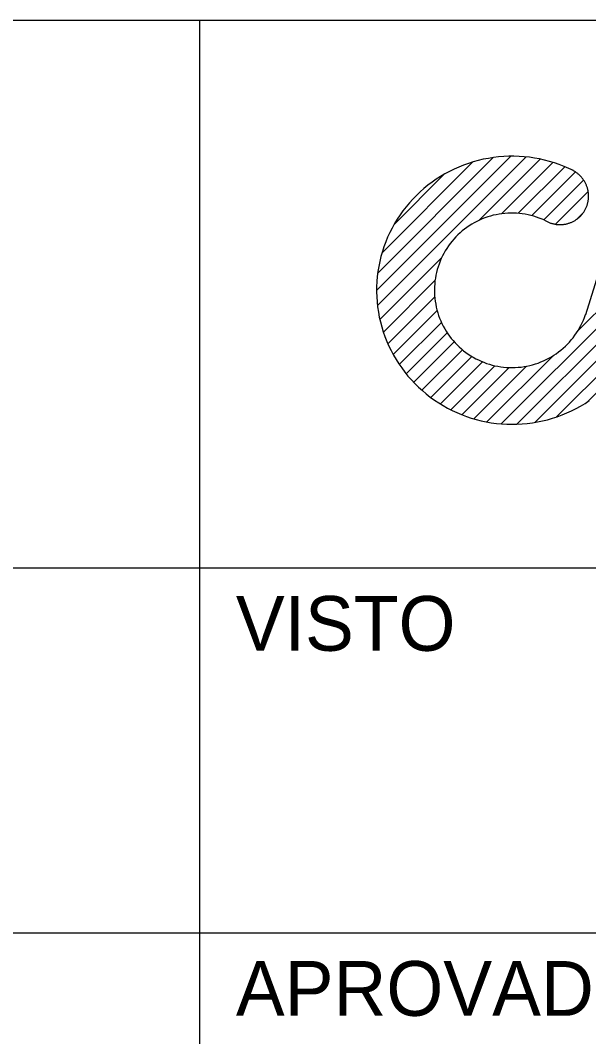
# Model space of a CAD drawing. Extents: x 563 to 1404, y 358 to 952.
# Drawn here: x 1178.67 to 1194.25, y 385.11 to 412.96 of the extents above; entities that cross this region are included whole.
import ezdxf

# ---------------------------------------------------------------- set-up
doc = ezdxf.new("R2010")
doc.units = 0
doc.layers.add('New Level (0)', color=7, linetype='Continuous')

# ---------------------------------------------------------------- blocks, each defined once
blk = doc.blocks.new('_U2')
at = {"layer": 'New Level (0)'}
for p, q in [((-15.391, 0.015), (-11.717, 3.689)), ((-15.367, -0.403), (-11.294, 3.67)), ((-15.36, 0.487), (-12.195, 3.653)), ((-12.329, 3.632), (-12.468, 3.605)), ((-12.19, 3.654), (-12.329, 3.632)), ((-12.05, 3.671), (-12.19, 3.654)), ((-11.909, 3.682), (-12.05, 3.671)), ((-11.768, 3.689), (-11.909, 3.682)), ((-11.627, 3.69), (-11.768, 3.689)), ((-11.486, 3.685), (-11.627, 3.69)), ((-11.345, 3.675), (-11.486, 3.685)), ((-11.205, 3.66), (-11.345, 3.675)), ((-11.065, 3.64), (-11.205, 3.66)), ((-10.927, 3.615), (-11.065, 3.64)), ((-15.242, 1.048), (-12.761, 3.529)), ((-13.139, 3.393), (-13.268, 3.335)), ((-13.008, 3.445), (-13.139, 3.393)), ((-12.876, 3.493), (-13.008, 3.445)), ((-12.741, 3.535), (-12.876, 3.493)), ((-12.605, 3.573), (-12.741, 3.535)), ((-12.468, 3.605), (-12.605, 3.573)), ((-12.593, 1.929), (-10.911, 3.611)), ((-11.966, 2.114), (-10.56, 3.52)), ((-11.512, 2.126), (-10.235, 3.403)), ((-10.789, 3.584), (-10.927, 3.615)), ((-10.653, 3.548), (-10.789, 3.584)), ((-10.518, 3.507), (-10.653, 3.548)), ((-10.384, 3.462), (-10.518, 3.507)), ((-10.253, 3.411), (-10.384, 3.462)), ((-10.124, 3.355), (-10.253, 3.411)), ((-9.996, 3.295), (-10.124, 3.355)), ((-14.914, 1.818), (-13.536, 3.196)), ((-13.639, 3.135), (-13.757, 3.059)), ((-13.518, 3.206), (-13.639, 3.135)), ((-13.394, 3.273), (-13.518, 3.206)), ((-13.268, 3.335), (-13.394, 3.273)), ((-11.135, 2.062), (-9.939, 3.258)), ((-9.996, 3.293), (-10.014, 3.303)), ((-9.979, 3.283), (-9.996, 3.293)), ((-9.962, 3.273), (-9.979, 3.283)), ((-9.945, 3.262), (-9.962, 3.273)), ((-9.928, 3.251), (-9.945, 3.262)), ((-9.912, 3.239), (-9.928, 3.251)), ((-9.896, 3.227), (-9.912, 3.239)), ((-9.88, 3.214), (-9.896, 3.227)), ((-9.865, 3.202), (-9.88, 3.214)), ((-9.85, 3.188), (-9.865, 3.202)), ((-9.835, 3.175), (-9.85, 3.188)), ((-9.82, 3.161), (-9.835, 3.175)), ((-9.806, 3.147), (-9.82, 3.161)), ((-9.793, 3.132), (-9.806, 3.147)), ((-9.779, 3.117), (-9.793, 3.132)), ((-9.766, 3.102), (-9.779, 3.117)), ((-9.754, 3.086), (-9.766, 3.102)), ((-9.742, 3.07), (-9.754, 3.086)), ((-9.73, 3.054), (-9.742, 3.07)), ((-14.094, 2.806), (-14.199, 2.713)), ((-13.985, 2.894), (-14.094, 2.806)), ((-13.873, 2.979), (-13.985, 2.894)), ((-13.757, 3.059), (-13.873, 2.979)), ((-10.809, 1.946), (-9.718, 3.036)), ((-9.719, 3.038), (-9.73, 3.054)), ((-9.708, 3.021), (-9.719, 3.038)), ((-9.697, 3.004), (-9.708, 3.021)), ((-9.687, 2.987), (-9.697, 3.004)), ((-9.677, 2.969), (-9.687, 2.987)), ((-9.668, 2.951), (-9.677, 2.969)), ((-9.659, 2.934), (-9.668, 2.951)), ((-8.572, 2.883), (-9.667, -0.651)), ((-9.651, 2.915), (-9.659, 2.934)), ((-9.643, 2.897), (-9.651, 2.915)), ((-9.636, 2.879), (-9.643, 2.897)), ((-9.629, 2.86), (-9.636, 2.879)), ((-9.622, 2.841), (-9.629, 2.86)), ((-9.616, 2.822), (-9.622, 2.841)), ((-9.611, 2.803), (-9.616, 2.822)), ((-9.605, 2.784), (-9.611, 2.803)), ((-14.399, 2.516), (-14.493, 2.412)), ((-14.301, 2.616), (-14.399, 2.516)), ((-14.199, 2.713), (-14.301, 2.616)), ((-10.486, 1.827), (-9.592, 2.72)), ((-9.601, 2.765), (-9.605, 2.784)), ((-9.597, 2.745), (-9.601, 2.765)), ((-9.593, 2.726), (-9.597, 2.745)), ((-9.59, 2.706), (-9.593, 2.726)), ((-9.587, 2.687), (-9.59, 2.706)), ((-9.589, 2.49), (-9.586, 2.509)), ((-9.585, 2.667), (-9.587, 2.687)), ((-9.586, 2.509), (-9.584, 2.529)), ((-9.584, 2.647), (-9.585, 2.667)), ((-9.583, 2.627), (-9.584, 2.647)), ((-9.584, 2.529), (-9.583, 2.548)), ((-9.582, 2.608), (-9.583, 2.627)), ((-9.583, 2.548), (-9.582, 2.568)), ((-9.582, 2.588), (-9.582, 2.608)), ((-9.582, 2.568), (-9.582, 2.588)), ((-14.583, 2.305), (-14.669, 2.194)), ((-14.493, 2.412), (-14.583, 2.305)), ((-9.682, 2.212), (-9.672, 2.229)), ((-9.672, 2.229), (-9.663, 2.246)), ((-9.663, 2.246), (-9.655, 2.264)), ((-9.655, 2.264), (-9.647, 2.282)), ((-9.647, 2.282), (-9.639, 2.3)), ((-9.639, 2.3), (-9.632, 2.318)), ((-9.632, 2.318), (-9.625, 2.337)), ((-9.625, 2.337), (-9.619, 2.355)), ((-9.619, 2.355), (-9.613, 2.374)), ((-9.613, 2.374), (-9.608, 2.393)), ((-9.608, 2.393), (-9.603, 2.412)), ((-9.603, 2.412), (-9.599, 2.431)), ((-9.599, 2.431), (-9.595, 2.451)), ((-9.595, 2.451), (-9.592, 2.47)), ((-9.592, 2.47), (-9.589, 2.49)), ((-14.827, 1.963), (-14.9, 1.844)), ((-14.75, 2.08), (-14.827, 1.963)), ((-14.669, 2.194), (-14.75, 2.08)), ((-12.497, 1.972), (-12.571, 1.94)), ((-12.423, 2.001), (-12.497, 1.972)), ((-12.347, 2.027), (-12.423, 2.001)), ((-12.271, 2.051), (-12.347, 2.027)), ((-12.193, 2.072), (-12.271, 2.051)), ((-12.115, 2.089), (-12.193, 2.072)), ((-12.036, 2.104), (-12.115, 2.089)), ((-11.957, 2.116), (-12.036, 2.104)), ((-11.878, 2.125), (-11.957, 2.116)), ((-11.798, 2.13), (-11.878, 2.125)), ((-11.718, 2.133), (-11.798, 2.13)), ((-11.637, 2.133), (-11.718, 2.133)), ((-11.557, 2.13), (-11.637, 2.133)), ((-11.477, 2.124), (-11.557, 2.13)), ((-11.398, 2.114), (-11.477, 2.124)), ((-11.319, 2.102), (-11.398, 2.114)), ((-11.24, 2.087), (-11.319, 2.102)), ((-11.162, 2.069), (-11.24, 2.087)), ((-11.085, 2.048), (-11.162, 2.069)), ((-11.008, 2.024), (-11.085, 2.048)), ((-10.933, 1.997), (-11.008, 2.024)), ((-10.858, 1.968), (-10.933, 1.997)), ((-10.785, 1.935), (-10.858, 1.968)), ((-9.936, 1.943), (-9.92, 1.954)), ((-9.92, 1.954), (-9.904, 1.965)), ((-9.909, 1.961), (-9.721, 2.149)), ((-9.904, 1.965), (-9.888, 1.977)), ((-9.888, 1.977), (-9.872, 1.989)), ((-9.872, 1.989), (-9.857, 2.001)), ((-9.857, 2.001), (-9.842, 2.014)), ((-9.842, 2.014), (-9.828, 2.027)), ((-9.828, 2.027), (-9.813, 2.041)), ((-9.813, 2.041), (-9.799, 2.055)), ((-9.799, 2.055), (-9.786, 2.069)), ((-9.786, 2.069), (-9.773, 2.084)), ((-9.773, 2.084), (-9.76, 2.099)), ((-9.76, 2.099), (-9.748, 2.114)), ((-9.748, 2.114), (-9.736, 2.129)), ((-9.736, 2.129), (-9.724, 2.145)), ((-9.724, 2.145), (-9.713, 2.161)), ((-9.713, 2.161), (-9.702, 2.178)), ((-9.702, 2.178), (-9.692, 2.195)), ((-9.692, 2.195), (-9.682, 2.212)), ((-14.967, 1.721), (-15.031, 1.597)), ((-14.9, 1.844), (-14.967, 1.721)), ((-12.981, 1.692), (-13.044, 1.642)), ((-12.917, 1.74), (-12.981, 1.692)), ((-12.851, 1.785), (-12.917, 1.74)), ((-12.783, 1.827), (-12.851, 1.785)), ((-12.714, 1.868), (-12.783, 1.827)), ((-12.643, 1.905), (-12.714, 1.868)), ((-12.571, 1.94), (-12.643, 1.905)), ((-10.788, 1.936), (-10.77, 1.926)), ((-10.77, 1.926), (-10.753, 1.916)), ((-10.753, 1.916), (-10.735, 1.907)), ((-10.735, 1.907), (-10.717, 1.898)), ((-10.717, 1.898), (-10.699, 1.89)), ((-10.699, 1.89), (-10.68, 1.882)), ((-10.68, 1.882), (-10.662, 1.874)), ((-10.662, 1.874), (-10.643, 1.867)), ((-10.643, 1.867), (-10.624, 1.86)), ((-10.624, 1.86), (-10.605, 1.854)), ((-10.605, 1.854), (-10.586, 1.849)), ((-10.586, 1.849), (-10.566, 1.843)), ((-10.566, 1.843), (-10.547, 1.839)), ((-10.547, 1.839), (-10.527, 1.834)), ((-10.527, 1.834), (-10.508, 1.831)), ((-10.508, 1.831), (-10.488, 1.827)), ((-10.488, 1.827), (-10.468, 1.824)), ((-10.468, 1.824), (-10.448, 1.822)), ((-10.448, 1.822), (-10.428, 1.82)), ((-10.428, 1.82), (-10.409, 1.819)), ((-10.409, 1.819), (-10.389, 1.818)), ((-10.389, 1.818), (-10.369, 1.818)), ((-10.369, 1.818), (-10.349, 1.818)), ((-10.349, 1.818), (-10.329, 1.819)), ((-10.329, 1.819), (-10.309, 1.82)), ((-10.309, 1.82), (-10.289, 1.821)), ((-10.289, 1.821), (-10.269, 1.824)), ((-10.269, 1.824), (-10.249, 1.826)), ((-10.249, 1.826), (-10.23, 1.829)), ((-10.23, 1.829), (-10.21, 1.833)), ((-10.21, 1.833), (-10.191, 1.837)), ((-10.191, 1.837), (-10.171, 1.841)), ((-10.171, 1.841), (-10.152, 1.846)), ((-10.152, 1.846), (-10.133, 1.852)), ((-10.133, 1.852), (-10.114, 1.858)), ((-10.114, 1.858), (-10.096, 1.864)), ((-10.096, 1.864), (-10.077, 1.871)), ((-10.077, 1.871), (-10.059, 1.879)), ((-10.059, 1.879), (-10.04, 1.887)), ((-10.04, 1.887), (-10.022, 1.895)), ((-10.022, 1.895), (-10.005, 1.904)), ((-10.005, 1.904), (-9.987, 1.913)), ((-9.987, 1.913), (-9.97, 1.922)), ((-9.97, 1.922), (-9.953, 1.932)), ((-9.953, 1.932), (-9.936, 1.943)), ((-15.089, 1.47), (-15.142, 1.341)), ((-15.031, 1.597), (-15.089, 1.47)), ((-13.273, 1.42), (-13.325, 1.359)), ((-13.219, 1.478), (-13.273, 1.42)), ((-13.163, 1.535), (-13.219, 1.478)), ((-13.104, 1.59), (-13.163, 1.535)), ((-13.044, 1.642), (-13.104, 1.59)), ((-9.882, -1.105), (-7.37, 1.406)), ((-15.19, 1.21), (-15.234, 1.077)), ((-15.142, 1.341), (-15.19, 1.21)), ((-13.467, 1.165), (-13.509, 1.098)), ((-13.422, 1.232), (-13.467, 1.165)), ((-13.375, 1.296), (-13.422, 1.232)), ((-13.325, 1.359), (-13.375, 1.296)), ((-15.272, 0.943), (-15.305, 0.807)), ((-15.302, -0.78), (-13.605, 0.917)), ((-15.234, 1.077), (-15.272, 0.943)), ((-13.62, 0.885), (-13.651, 0.812)), ((-13.586, 0.957), (-13.62, 0.885)), ((-13.549, 1.028), (-13.586, 0.957)), ((-13.509, 1.098), (-13.549, 1.028)), ((-15.333, 0.671), (-15.355, 0.533)), ((-15.305, 0.807), (-15.333, 0.671)), ((-13.729, 0.585), (-13.749, 0.508)), ((-13.706, 0.662), (-13.729, 0.585)), ((-13.68, 0.737), (-13.706, 0.662)), ((-13.651, 0.812), (-13.68, 0.737)), ((-11.977, -3.642), (-7.564, 0.771)), ((-15.372, 0.395), (-15.384, 0.256)), ((-15.355, 0.533), (-15.372, 0.395)), ((-15.206, -1.126), (-13.788, 0.292)), ((-13.78, 0.351), (-13.791, 0.272)), ((-13.766, 0.43), (-13.78, 0.351)), ((-13.749, 0.508), (-13.766, 0.43)), ((-15.39, 0.116), (-15.392, -0.023)), ((-15.384, 0.256), (-15.39, 0.116)), ((-13.805, 0.113), (-13.807, 0.033)), ((-13.807, 0.033), (-13.806, -0.047)), ((-13.8, 0.193), (-13.805, 0.113)), ((-13.791, 0.272), (-13.8, 0.193)), ((-11.545, -3.652), (-7.758, 0.135)), ((-15.392, -0.023), (-15.387, -0.162)), ((-15.387, -0.162), (-15.378, -0.301)), ((-15.083, -1.445), (-13.799, -0.161)), ((-13.806, -0.047), (-13.802, -0.127)), ((-13.802, -0.127), (-13.795, -0.206)), ((-13.795, -0.206), (-13.785, -0.285)), ((-15.378, -0.301), (-15.363, -0.44)), ((-15.363, -0.44), (-15.343, -0.578)), ((-14.937, -1.741), (-13.732, -0.536)), ((-13.785, -0.285), (-13.772, -0.364)), ((-13.772, -0.364), (-13.756, -0.442)), ((-13.756, -0.442), (-13.737, -0.52)), ((-13.737, -0.52), (-13.716, -0.597)), ((-11.053, -3.602), (-7.952, -0.501)), ((-15.343, -0.578), (-15.317, -0.715)), ((-15.317, -0.715), (-15.286, -0.851)), ((-13.716, -0.597), (-13.691, -0.673)), ((-13.691, -0.673), (-13.664, -0.748)), ((-13.664, -0.748), (-13.633, -0.822)), ((-13.633, -0.822), (-13.6, -0.894)), ((-9.755, -0.872), (-9.723, -0.799)), ((-9.723, -0.799), (-9.693, -0.725)), ((-9.693, -0.725), (-9.667, -0.649)), ((-15.286, -0.851), (-15.25, -0.986)), ((-15.25, -0.986), (-15.209, -1.119)), ((-14.77, -2.015), (-13.615, -0.861)), ((-13.6, -0.894), (-13.564, -0.966)), ((-13.564, -0.966), (-13.526, -1.036)), ((-13.526, -1.036), (-13.485, -1.104)), ((-13.485, -1.104), (-13.441, -1.171)), ((-9.911, -1.151), (-9.868, -1.083)), ((-9.868, -1.083), (-9.828, -1.014)), ((-9.828, -1.014), (-9.79, -0.944)), ((-9.79, -0.944), (-9.755, -0.872)), ((-15.209, -1.119), (-15.163, -1.251)), ((-15.163, -1.251), (-15.112, -1.381)), ((-15.112, -1.381), (-15.055, -1.509)), ((-14.582, -2.269), (-13.458, -1.145)), ((-13.441, -1.171), (-13.395, -1.237)), ((-13.395, -1.237), (-13.346, -1.3)), ((-13.346, -1.3), (-13.295, -1.362)), ((-13.295, -1.362), (-13.242, -1.421)), ((-10.463, -3.453), (-8.146, -1.137)), ((-10.107, -1.403), (-10.055, -1.343)), ((-10.055, -1.343), (-10.004, -1.281)), ((-10.004, -1.281), (-9.956, -1.216)), ((-9.956, -1.216), (-9.911, -1.151)), ((-15.055, -1.509), (-14.994, -1.634)), ((-14.994, -1.634), (-14.928, -1.758)), ((-14.375, -2.504), (-13.265, -1.395)), ((-14.15, -2.721), (-13.04, -1.611)), ((-13.242, -1.421), (-13.186, -1.479)), ((-13.186, -1.479), (-13.128, -1.534)), ((-13.128, -1.534), (-13.069, -1.588)), ((-13.069, -1.588), (-13.007, -1.638)), ((-13.007, -1.638), (-12.944, -1.687)), ((-10.402, -1.672), (-10.339, -1.623)), ((-10.339, -1.623), (-10.278, -1.571)), ((-10.278, -1.571), (-10.219, -1.517)), ((-10.219, -1.517), (-10.162, -1.461)), ((-10.162, -1.461), (-10.107, -1.403)), ((-14.928, -1.758), (-14.858, -1.878)), ((-14.858, -1.878), (-14.783, -1.996)), ((-13.906, -2.919), (-12.781, -1.795)), ((-13.642, -3.097), (-12.487, -1.942)), ((-12.944, -1.687), (-12.878, -1.733)), ((-12.878, -1.733), (-12.811, -1.777)), ((-12.811, -1.777), (-12.742, -1.818)), ((-12.742, -1.818), (-12.672, -1.857)), ((-12.672, -1.857), (-12.601, -1.892)), ((-12.601, -1.892), (-12.528, -1.926)), ((-12.528, -1.926), (-12.454, -1.956)), ((-12.367, -3.59), (-10.551, -1.774)), ((-10.964, -1.975), (-10.889, -1.947)), ((-10.889, -1.947), (-10.815, -1.916)), ((-10.815, -1.916), (-10.743, -1.882)), ((-10.743, -1.882), (-10.671, -1.845)), ((-10.671, -1.845), (-10.602, -1.805)), ((-10.602, -1.805), (-10.534, -1.764)), ((-10.534, -1.764), (-10.467, -1.719)), ((-10.467, -1.719), (-10.402, -1.672)), ((-14.783, -1.996), (-14.703, -2.111)), ((-14.703, -2.111), (-14.619, -2.223)), ((-14.619, -2.223), (-14.531, -2.332)), ((-13.358, -3.255), (-12.151, -2.048)), ((-13.053, -3.392), (-11.759, -2.099)), ((-12.723, -3.504), (-11.281, -2.062)), ((-12.454, -1.956), (-12.378, -1.984)), ((-12.378, -1.984), (-12.302, -2.008)), ((-12.302, -2.008), (-12.225, -2.03)), ((-12.225, -2.03), (-12.147, -2.049)), ((-12.147, -2.049), (-12.069, -2.065)), ((-12.069, -2.065), (-11.99, -2.078)), ((-11.99, -2.078), (-11.91, -2.088)), ((-11.91, -2.088), (-11.83, -2.095)), ((-11.83, -2.095), (-11.75, -2.099)), ((-11.75, -2.099), (-11.67, -2.1)), ((-11.67, -2.1), (-11.59, -2.098)), ((-11.59, -2.098), (-11.51, -2.093)), ((-11.51, -2.093), (-11.431, -2.085)), ((-11.431, -2.085), (-11.351, -2.074)), ((-11.351, -2.074), (-11.272, -2.06)), ((-11.272, -2.06), (-11.194, -2.043)), ((-11.194, -2.043), (-11.116, -2.024)), ((-11.116, -2.024), (-11.04, -2.001)), ((-11.04, -2.001), (-10.964, -1.975)), ((-9.589, -3.021), (-8.572, -2.005)), ((-14.531, -2.332), (-14.438, -2.438)), ((-14.438, -2.438), (-14.342, -2.54)), ((-14.342, -2.54), (-14.242, -2.638)), ((-14.242, -2.638), (-14.138, -2.732)), ((-14.138, -2.732), (-14.03, -2.822)), ((-14.03, -2.822), (-13.92, -2.909)), ((-13.92, -2.909), (-13.806, -2.991)), ((-13.806, -2.991), (-13.688, -3.069)), ((-9.679, -3.081), (-9.562, -3.004)), ((-13.688, -3.069), (-13.568, -3.142)), ((-13.568, -3.142), (-13.446, -3.211)), ((-13.446, -3.211), (-13.32, -3.275)), ((-13.32, -3.275), (-13.193, -3.334)), ((-13.193, -3.334), (-13.063, -3.389)), ((-10.177, -3.343), (-10.049, -3.285)), ((-10.049, -3.285), (-9.923, -3.221)), ((-9.923, -3.221), (-9.8, -3.153)), ((-9.8, -3.153), (-9.679, -3.081)), ((-13.063, -3.389), (-12.931, -3.438)), ((-12.931, -3.438), (-12.797, -3.483)), ((-12.797, -3.483), (-12.662, -3.522)), ((-12.662, -3.522), (-12.525, -3.557)), ((-12.525, -3.557), (-12.387, -3.586)), ((-12.387, -3.586), (-12.248, -3.61)), ((-12.248, -3.61), (-12.108, -3.629)), ((-11.263, -3.632), (-11.123, -3.614)), ((-11.123, -3.614), (-10.984, -3.59)), ((-10.984, -3.59), (-10.846, -3.562)), ((-10.846, -3.562), (-10.709, -3.528)), ((-10.709, -3.528), (-10.573, -3.489)), ((-10.573, -3.489), (-10.439, -3.446)), ((-10.439, -3.446), (-10.307, -3.397)), ((-10.307, -3.397), (-10.177, -3.343)), ((-12.108, -3.629), (-11.968, -3.643)), ((-11.968, -3.643), (-11.827, -3.651)), ((-11.827, -3.651), (-11.686, -3.654)), ((-11.686, -3.654), (-11.545, -3.652)), ((-11.545, -3.652), (-11.404, -3.645)), ((-11.404, -3.645), (-11.263, -3.632))]:
    blk.add_line(p, q, dxfattribs=at)

msp = doc.modelspace()

# ---------------------------------------------------------------- linework, layer by layer
at = {"layer": 'New Level (0)'}
for p, q in [((572.577, 412.956), (1393.577, 412.956)), ((1183.577, 412.956), (1183.577, 367.956)), ((1143.577, 397.956), (1325.577, 397.956)), ((1143.577, 387.956), (1223.577, 387.956))]:
    msp.add_line(p, q, dxfattribs=at)

# ---------------------------------------------------------------- block references
msp.add_blockref('_U2', (1203.825, 405.543), dxfattribs=at)

# ---------------------------------------------------------------- texts
for s, p in [('VISTO', (1184.577, 395.685)), ('APROVADO', (1184.577, 385.685))]:
    msp.add_text(s, height=1.5, dxfattribs=at).set_placement(p)

doc.saveas('drawing.dxf')
